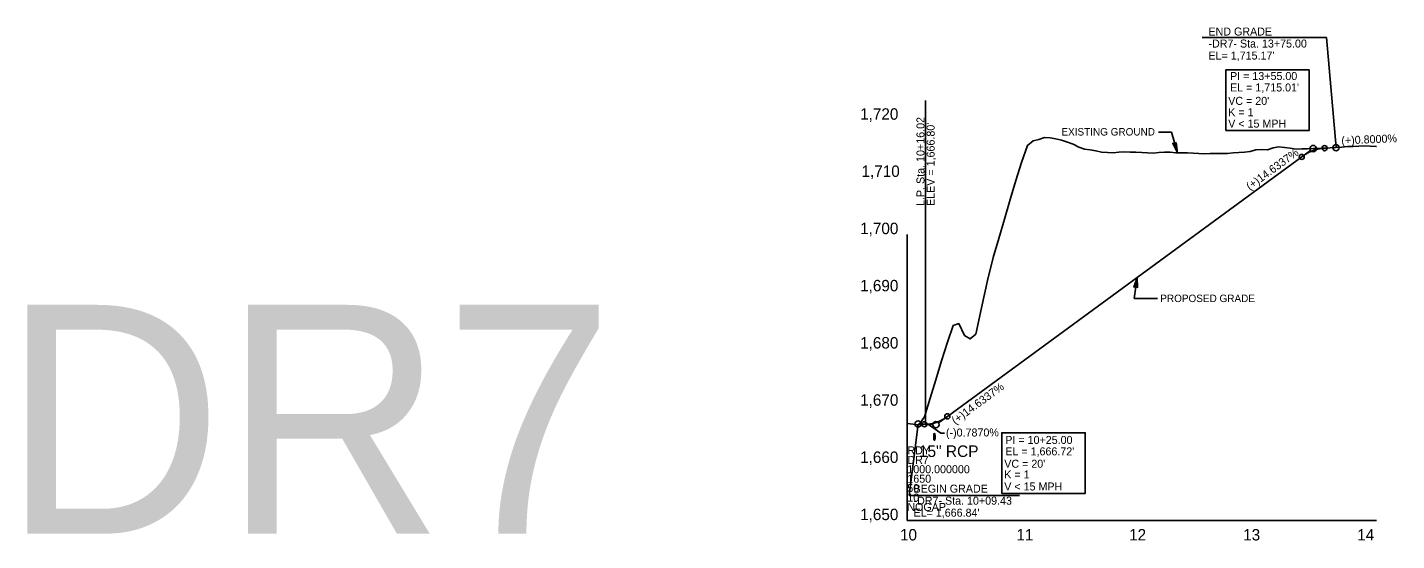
# Model space of a CAD drawing. Extents: x 498575 to 532350, y 405181 to 484585.
# Drawn here: x 526514 to 527712, y 467449 to 467898 of the extents above; entities that cross this region are included whole.
import ezdxf

# ---------------------------------------------------------------- set-up
doc = ezdxf.new("R2010")
doc.units = 0
for name, color, linetype in [('Exist Profile Cell', 7, 'Continuous'), ('Exist Vertical Profile Ground Line', 7, 'Continuous'), ('Exist Vertical Profile Horizontal Axis Label Major', 7, 'Continuous'), ('Exist Vertical Profile Vertical Axis Label', 7, 'Continuous'), ('Prop Drainage Structure Pipe Welded Steel 54in Label', 7, 'Continuous'), ('Prop Grid Mask', 7, 'Continuous'), ('Prop PFL Text', 7, 'Continuous'), ('Prop Vertical Profile Curve Label', 7, 'Continuous'), ('Prop Vertical Profile Grade', 7, 'Continuous'), ('Prop Vertical Profile Grade Label', 7, 'Continuous'), ('Prop Vertical Profile Strip Grade', 7, 'Continuous'), ('Prop VPI Label', 7, 'Continuous'), ('Scratch_Level_7', 7, 'Continuous')]:
    doc.layers.add(name, color=color, linetype=linetype)

msp = doc.modelspace()

# ---------------------------------------------------------------- linework, layer by layer
at = {"layer": 'Exist Profile Cell'}
for q in [(527283.8, 467716.6), (527694.1, 467466.6), (527283.8, 467466.6)]:
    msp.add_line((527283.8, 467466.6), q, dxfattribs=at)
at = {"layer": 'Exist Vertical Profile Ground Line'}
msp.add_lwpolyline([(527283.8, 467551.5), (527288.8, 467550.8), (527293.8, 467550.2), (527298.8, 467557.3), (527303.8, 467573.4), (527308.8, 467589.5), (527313.8, 467606.1), (527318.8, 467622.4), (527323.8, 467637.1), (527328.8, 467638.7), (527333.8, 467628.3), (527338.8, 467625.3), (527343.8, 467629.5), (527348.8, 467652.6), (527353.8, 467676.5), (527358.8, 467696.6), (527363.8, 467713.2), (527368.8, 467729.9), (527373.8, 467747.3), (527378.8, 467763.9), (527383.8, 467779.5), (527388.8, 467794.4), (527393.8, 467798.5), (527398.8, 467799.7), (527403.8, 467801.3), (527408.8, 467801), (527413.8, 467800.1), (527418.8, 467799), (527423.8, 467797.4), (527428.8, 467795.4), (527433.8, 467792.8), (527438.8, 467791.2), (527443.8, 467790.5), (527448.8, 467789.8), (527453.8, 467788.5), (527458.8, 467788.3), (527463.8, 467788.1), (527468.8, 467788.5), (527473.8, 467788.8), (527478.8, 467788.5), (527483.8, 467788.4), (527488.8, 467788.2), (527493.8, 467788.1), (527498.8, 467787.8), (527503.8, 467788.2), (527508.8, 467788.4), (527513.8, 467788.5), (527518.8, 467788.1), (527523.8, 467788), (527528.8, 467788), (527533.8, 467787.7), (527538.8, 467787.4), (527543.8, 467787), (527548.8, 467787.5), (527553.8, 467787.3), (527558.8, 467787.3), (527563.8, 467787.5), (527568.8, 467788), (527573.8, 467788.3), (527578.8, 467788.4), (527583.8, 467789.1), (527588.8, 467790.5), (527593.8, 467790.8), (527598.8, 467790.7), (527603.8, 467792.2), (527608.8, 467793.2), (527613.8, 467792.7), (527618.8, 467792), (527623.8, 467791.3), (527628.8, 467791.4), (527633.8, 467791.6), (527638.8, 467791.8), (527643.8, 467791.8), (527648.8, 467791.8), (527653.8, 467792.3), (527658.8, 467792.5), (527663.8, 467793), (527668.8, 467793.6), (527673.8, 467793.6), (527678.8, 467793.7), (527683.8, 467794), (527688.8, 467793.7), (527693.8, 467793.5), (527694.1, 467793.5)], dxfattribs=at)
at = {"layer": 'Prop Drainage Structure Pipe Welded Steel 54in Label'}
msp.add_ellipse((527307.5, 467539.8), major_axis=(0, 3.12), ratio=0.2, dxfattribs=at)
at = {"layer": 'Prop Grid Mask'}
for points in [[(527562.3, 467807.4), (527635.3, 467807.4), (527635.3, 467860.5), (527562.3, 467860.5)], [(527366.4, 467490.2), (527439.4, 467490.2), (527439.4, 467543.3), (527366.4, 467543.3)]]:
    msp.add_lwpolyline(points, close=True, dxfattribs=at)
at = {"layer": 'Prop PFL Text'}
for p, q in [((527514.8, 467805.9), (527503.6, 467805.9)), ((527520.2, 467788.1), (527514.8, 467805.9)), ((527482.3, 467660.5), (527484.9, 467679.1)), ((527502.7, 467660.5), (527482.3, 467660.5))]:
    msp.add_line(p, q, dxfattribs=at)
for points in [[(527519.1, 467797.1), (527520.2, 467788.1), (527516, 467796.3), (527517.9, 467795.6)], [(527485.2, 467670), (527484.9, 467679.1), (527482, 467670.4), (527483.8, 467671.3)]]:
    msp.add_lwpolyline(points, close=True, dxfattribs=at)
at = {"layer": 'Prop Vertical Profile Curve Label'}
for centre in [(527648.8, 467792.1), (527628.8, 467784.4), (527298.8, 467550.7), (527318.8, 467557.6)]:
    msp.add_circle(centre, 2.25, dxfattribs=at)
at = {"layer": 'Prop Vertical Profile Grade'}
for p, q in [((527648.8, 467792.1), (527658.8, 467792.5)), ((527318.8, 467557.6), (527628.8, 467784.4)), ((527293.2, 467550.9), (527298.8, 467550.7))]:
    msp.add_line(p, q, dxfattribs=at)
for points in [[(527628.8, 467784.4), (527629.2, 467784.7), (527629.6, 467785), (527630, 467785.2), (527630.4, 467785.5), (527630.8, 467785.8), (527631.2, 467786.1), (527631.6, 467786.3), (527632, 467786.6), (527632.4, 467786.8), (527632.8, 467787), (527633.2, 467787.3), (527633.6, 467787.5), (527634, 467787.7), (527634.4, 467788), (527634.8, 467788.2), (527635.2, 467788.4), (527635.6, 467788.6), (527636, 467788.8), (527636.4, 467789), (527636.8, 467789.1), (527637.2, 467789.3), (527637.6, 467789.5), (527638, 467789.7), (527638.4, 467789.8), (527638.8, 467790), (527639.2, 467790.1), (527639.6, 467790.3), (527640, 467790.4), (527640.4, 467790.6), (527640.8, 467790.7), (527641.2, 467790.8), (527641.6, 467790.9), (527642, 467791), (527642.4, 467791.1), (527642.8, 467791.3), (527643.2, 467791.3), (527643.6, 467791.4), (527644, 467791.5), (527644.4, 467791.6), (527644.8, 467791.7), (527645.2, 467791.7), (527645.6, 467791.8), (527646, 467791.9), (527646.4, 467791.9), (527646.8, 467792), (527647.2, 467792), (527647.6, 467792), (527648, 467792.1), (527648.4, 467792.1), (527648.8, 467792.1)], [(527298.8, 467550.7), (527299.2, 467550.6), (527299.6, 467550.6), (527300, 467550.6), (527300.4, 467550.6), (527300.8, 467550.6), (527301.2, 467550.7), (527301.6, 467550.7), (527302, 467550.7), (527302.4, 467550.8), (527302.8, 467550.8), (527303.2, 467550.9), (527303.6, 467550.9), (527304, 467551), (527304.4, 467551), (527304.8, 467551.1), (527305.2, 467551.2), (527305.6, 467551.3), (527306, 467551.4), (527306.4, 467551.5), (527306.8, 467551.6), (527307.2, 467551.7), (527307.6, 467551.8), (527308, 467551.9), (527308.4, 467552), (527308.8, 467552.2), (527309.2, 467552.3), (527309.6, 467552.5), (527310, 467552.6), (527310.4, 467552.8), (527310.8, 467553), (527311.2, 467553.1), (527311.6, 467553.3), (527312, 467553.5), (527312.4, 467553.7), (527312.8, 467553.9), (527313.2, 467554.1), (527313.6, 467554.3), (527314, 467554.5), (527314.4, 467554.7), (527314.8, 467555), (527315.2, 467555.2), (527315.6, 467555.4), (527316, 467555.7), (527316.4, 467555.9), (527316.8, 467556.2), (527317.2, 467556.5), (527317.6, 467556.7), (527318, 467557), (527318.4, 467557.3), (527318.8, 467557.6)]]:
    msp.add_spline(points, degree=3, dxfattribs=at)
at = {"layer": 'Prop Vertical Profile Grade Label'}
msp.add_lwpolyline([(527316.4, 467542.8), (527313, 467542.8), (527302.4, 467550.5)], dxfattribs=at)
at = {"layer": 'Prop Vertical Profile Strip Grade'}
msp.add_line((527299.8, 467550.6), (527299.8, 467833.6), dxfattribs=at)
at = {"layer": 'Prop VPI Label'}
for p, q in [((527541.7, 467888.8), (527650.4, 467888.8)), ((527658.8, 467792.5), (527650.4, 467888.8)), ((527628.8, 467784.4), (527636.6, 467790.1)), ((527648.8, 467792.1), (527641.5, 467791.8)), ((527318.8, 467557.6), (527311, 467551.9)), ((527285.5, 467488.4), (527293.2, 467550.9)), ((527298.8, 467550.7), (527306, 467550.4)), ((527285.5, 467488.4), (527381.9, 467488.4))]:
    msp.add_line(p, q, dxfattribs=at)
for centre in [(527638.8, 467791.7), (527658.8, 467792.5), (527293.2, 467550.9), (527308.8, 467550.3)]:
    msp.add_circle(centre, 2.75, dxfattribs=at)

# ---------------------------------------------------------------- texts
at = {"layer": 'Exist Profile Cell'}
for s, p in [('RDY', (527283.8, 467524.4)), ('DR7', (527283.8, 467516.1)), ('1000.000000', (527283.8, 467507.9)), ('1650', (527283.8, 467499.6)), ('50', (527283.8, 467491.4)), ('10', (527283.8, 467483.1)), ('NOGAP', (527283.8, 467474.9))]:
    msp.add_text(s, height=7, dxfattribs=at).set_placement(p)
at = {"layer": 'Exist Vertical Profile Horizontal Axis Label Major'}
for s, p in [('10', (527277.4, 467449.1)), ('11', (527379.2, 467449.1)), ('12', (527477.8, 467449.1)), ('13', (527577.6, 467449.1)), ('14', (527677.4, 467449.1))]:
    msp.add_text(s, height=10, dxfattribs=at).set_placement(p)
at = {"layer": 'Exist Vertical Profile Vertical Axis Label'}
for s, p in [('1,720', (527242.5, 467816.9)), ('1,710', (527243.7, 467766.9)), ('1,700', (527242.5, 467716.9)), ('1,690', (527242.5, 467666.9)), ('1,680', (527242.5, 467616.9)), ('1,670', (527242.5, 467566.9)), ('1,660', (527242.5, 467516.9)), ('1,650', (527242.5, 467466.9))]:
    msp.add_text(s, height=10, dxfattribs=at).set_placement(p)
at = {"layer": 'Prop Drainage Structure Pipe Welded Steel 54in Label'}
msp.add_text('15" RCP', height=10.12, dxfattribs=at).set_placement((527293.9, 467522.1))
at = {"layer": 'Prop PFL Text'}
for s, p in [('EXISTING GROUND', (527418.6, 467803.1)), ('PROPOSED GRADE', (527505.1, 467657.5))]:
    msp.add_text(s, height=6.516, dxfattribs=at).set_placement(p)
at = {"layer": 'Prop Vertical Profile Curve Label'}
for s, p in [("VC = 20'", (527564.5, 467829.9)), ('V < 15 MPH ', (527564.5, 467810)), ("VC = 20'", (527368.6, 467512.7)), ('K = 1', (527368.6, 467503.3)), ('V < 15 MPH ', (527368.6, 467492.8))]:
    msp.add_text(s, height=7, dxfattribs=at).set_placement(p)
at = {"layer": 'Prop Vertical Profile Grade Label'}
for s, rotation, p in [('(+)0.8000%', 2.2905, (527663.6, 467795.3)), ('(+)14.6337%', 36.1924, (527583.4, 467754.9)), ('(+)14.6337%', 36.1924, (527325.7, 467550.2)), ('(-)0.7870%', 0.2075, (527317.6, 467539.9))]:
    msp.add_text(s, height=7, rotation=rotation, dxfattribs=at).set_placement(p)
at = {"layer": 'Prop Vertical Profile Strip Grade'}
for s, p in [('L.P. Sta. 10+16.02', (527298.8, 467741.5)), ("ELEV = 1,666.80'", (527307.7, 467741.5))]:
    msp.add_text(s, height=7, rotation=90, dxfattribs=at).set_placement(p)
at = {"layer": 'Prop VPI Label'}
for s, p in [('END GRADE', (527547.2, 467890.5)), ('-DR7- Sta. 13+75.00', (527547.2, 467880)), ("EL= 1,715.17'", (527547.2, 467869.5)), ('PI = 13+55.00', (527566.1, 467851.6)), ("EL = 1,715.01'", (527566.1, 467841.6)), ('K = 1', (527564.5, 467820)), ('PI = 10+25.00', (527369.5, 467533.5)), ("EL = 1,666.72'", (527369.5, 467523.5)), ('BEGIN GRADE', (527289.2, 467490.9)), ('-DR7- Sta. 10+09.43', (527289.2, 467480.4)), ("EL= 1,666.84'", (527289.2, 467469.9))]:
    msp.add_text(s, height=7, dxfattribs=at).set_placement(p)
at = {"layer": 'Scratch_Level_7'}
msp.add_text('DR7', height=200, dxfattribs=at).set_placement((526492.1, 467455.1))

doc.saveas('drawing.dxf')
